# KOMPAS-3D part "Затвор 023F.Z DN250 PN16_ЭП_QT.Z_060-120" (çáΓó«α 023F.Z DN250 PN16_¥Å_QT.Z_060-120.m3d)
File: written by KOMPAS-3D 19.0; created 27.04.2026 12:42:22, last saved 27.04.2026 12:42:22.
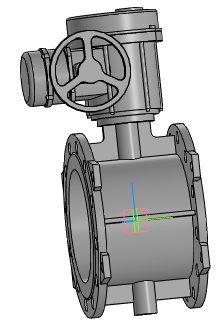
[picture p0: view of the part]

Document properties: Полное имя файла: Затвор 023F.Z DN250 PN16 + электропривод QT.Z060-120.a3d

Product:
- Part/product: Затвор 023F.Z DN250 PN16_ЭП_QT.Z_060-120
    Масса: 130.98
  - Body: Тело 1
      Масса: 131.281

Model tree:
1. Операция без истории:1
